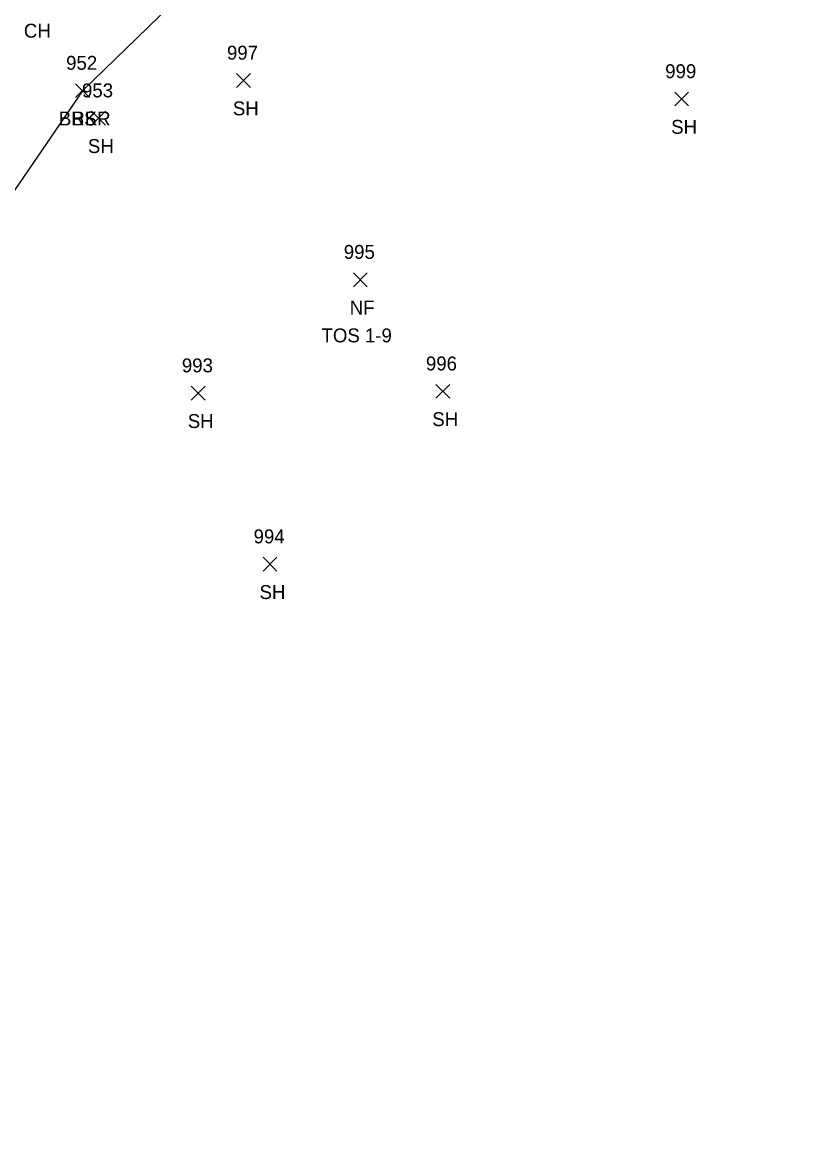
# Model space of a CAD drawing. Extents: x 1528286 to 1556263, y 492387 to 508952.
# Drawn here: x 1528541.2 to 1528653.3, y 492464.6 to 492624 of the extents above; entities that cross this region are included whole.
import ezdxf

# ---------------------------------------------------------------- set-up
doc = ezdxf.new("R2010")
doc.units = 0
for name, color, linetype in [('L_A', 7, 'Continuous'), ('L_C', 7, 'Continuous'), ('L_I', 7, 'Continuous'), ('L_TIC', 7, 'Continuous'), ('LAWE', 7, 'Continuous'), ('LELB', 7, 'Continuous')]:
    doc.layers.add(name, color=color, linetype=linetype)

msp = doc.modelspace()

# ---------------------------------------------------------------- linework, layer by layer
at = {"layer": 'L_TIC'}
for points in [[(1528572.03, 492614.6), (1528574.03, 492616.6)], [(1528574.03, 492614.6), (1528572.03, 492616.6)], [(1528572.03, 492614.6), (1528574.03, 492616.6)], [(1528574.03, 492614.6), (1528572.03, 492616.6)], [(1528548.93, 492613.14), (1528550.93, 492615.14)], [(1528550.93, 492613.14), (1528548.93, 492615.14)], [(1528548.93, 492613.14), (1528550.93, 492615.14)], [(1528550.93, 492613.14), (1528548.93, 492615.14)], [(1528548.93, 492613.14), (1528550.93, 492615.14)], [(1528550.93, 492613.14), (1528548.93, 492615.14)], [(1528548.93, 492613.14), (1528550.93, 492615.14)], [(1528550.93, 492613.14), (1528548.93, 492615.14)], [(1528635.01, 492611.94), (1528637.01, 492613.94)], [(1528637.01, 492611.94), (1528635.01, 492613.94)], [(1528635.01, 492611.94), (1528637.01, 492613.94)], [(1528637.01, 492611.94), (1528635.01, 492613.94)], [(1528551.2, 492609.18), (1528553.2, 492611.18)], [(1528553.2, 492609.18), (1528551.2, 492611.18)], [(1528551.2, 492609.18), (1528553.2, 492611.18)], [(1528553.2, 492609.18), (1528551.2, 492611.18)], [(1528588.83, 492585.97), (1528590.83, 492587.97)], [(1528590.83, 492585.97), (1528588.83, 492587.97)], [(1528588.83, 492585.97), (1528590.83, 492587.97)], [(1528590.83, 492585.97), (1528588.83, 492587.97)], [(1528600.68, 492569.93), (1528602.68, 492571.93)], [(1528602.68, 492569.93), (1528600.68, 492571.93)], [(1528600.68, 492569.93), (1528602.68, 492571.93)], [(1528602.68, 492569.93), (1528600.68, 492571.93)], [(1528565.55, 492569.66), (1528567.55, 492571.66)], [(1528567.55, 492569.66), (1528565.55, 492571.66)], [(1528565.55, 492569.66), (1528567.55, 492571.66)], [(1528567.55, 492569.66), (1528565.55, 492571.66)], [(1528575.86, 492545.08), (1528577.86, 492547.08)], [(1528577.86, 492545.08), (1528575.86, 492547.08)], [(1528575.86, 492545.08), (1528577.86, 492547.08)], [(1528577.86, 492545.08), (1528575.86, 492547.08)]]:
    msp.add_lwpolyline(points, dxfattribs=at)
at = {"layer": 'LAWE'}
msp.add_lwpolyline([(1528645.44, 492730.64), (1528651.62, 492718.64), (1528645.74, 492704.77), (1528631.81, 492684.8), (1528615.48, 492671.09), (1528597.13, 492648.32), (1528570.32, 492633.93), (1528549.93, 492614.14), (1528527.11, 492580.82), (1528486.91, 492550.69), (1528466.24, 492548.44), (1528453.39, 492536.12), (1528428.92, 492520.07), (1528405.49, 492507.44), (1528391.91, 492487.09), (1528384.54, 492464.65)], dxfattribs=at)
msp.add_lwpolyline([(1528645.44, 492730.64), (1528651.62, 492718.64), (1528645.74, 492704.77), (1528631.81, 492684.8), (1528615.48, 492671.09), (1528597.13, 492648.32), (1528570.32, 492633.93), (1528549.93, 492614.14), (1528527.11, 492580.82), (1528486.91, 492550.69), (1528466.24, 492548.44), (1528453.39, 492536.12), (1528428.92, 492520.07), (1528405.49, 492507.44), (1528391.91, 492487.09), (1528384.54, 492464.65)], dxfattribs=at)
at = {"layer": 'LELB'}
msp.add_lwpolyline([(1528653.27, 492717.81), (1528645.74, 492704.77), (1528631.81, 492684.8), (1528615.48, 492671.09), (1528597.13, 492648.32), (1528570.32, 492633.93), (1528549.93, 492614.14), (1528527.11, 492580.82), (1528486.91, 492550.69), (1528472.87, 492532.39)], dxfattribs=at)
msp.add_lwpolyline([(1528653.27, 492717.81), (1528645.74, 492704.77), (1528631.81, 492684.8), (1528615.48, 492671.09), (1528597.13, 492648.32), (1528570.32, 492633.93), (1528549.93, 492614.14), (1528527.11, 492580.82), (1528486.91, 492550.69), (1528472.87, 492532.39)], dxfattribs=at)

# ---------------------------------------------------------------- texts
at = {"layer": 'L_A'}
for s, p in [('CH', (1528541.49, 492621.76)), ('CH', (1528541.49, 492621.76)), ('SH', (1528571.52, 492610.6)), ('SH', (1528571.52, 492610.6)), ('BRKR', (1528546.52, 492609.14)), ('BRKR', (1528546.52, 492609.14)), ('BS', (1528548.37, 492609.14)), ('BS', (1528548.37, 492609.14)), ('SH', (1528634.5, 492607.94)), ('SH', (1528634.5, 492607.94)), ('SH', (1528550.69, 492605.18)), ('SH', (1528550.69, 492605.18)), ('NF', (1528588.31, 492581.97)), ('NF', (1528588.31, 492581.97)), ('SH', (1528565.04, 492565.66)), ('SH', (1528565.04, 492565.66)), ('SH', (1528600.17, 492565.93)), ('SH', (1528600.17, 492565.93)), ('SH', (1528575.35, 492541.08)), ('SH', (1528575.35, 492541.08))]:
    msp.add_text(s, height=2, dxfattribs=at).set_placement(p)
at = {"layer": 'L_C'}
msp.add_text('TOS 1-9', height=2, dxfattribs=at).set_placement((1528584.26, 492577.97))
msp.add_text('TOS 1-9', height=2, dxfattribs=at).set_placement((1528584.26, 492577.97))
at = {"layer": 'L_I'}
for s, p in [('997', (1528570.67, 492618.6)), ('997', (1528570.67, 492618.6)), ('952', (1528547.56, 492617.14)), ('952', (1528547.56, 492617.14)), ('952', (1528547.56, 492617.14)), ('952', (1528547.56, 492617.14)), ('999', (1528633.64, 492615.94)), ('999', (1528633.64, 492615.94)), ('953', (1528549.84, 492613.18)), ('953', (1528549.84, 492613.18)), ('995', (1528587.46, 492589.97)), ('995', (1528587.46, 492589.97)), ('993', (1528564.19, 492573.66)), ('993', (1528564.19, 492573.66)), ('996', (1528599.26, 492573.93)), ('996', (1528599.26, 492573.93)), ('994', (1528574.5, 492549.08)), ('994', (1528574.5, 492549.08))]:
    msp.add_text(s, height=2, dxfattribs=at).set_placement(p)

doc.saveas('drawing.dxf')
